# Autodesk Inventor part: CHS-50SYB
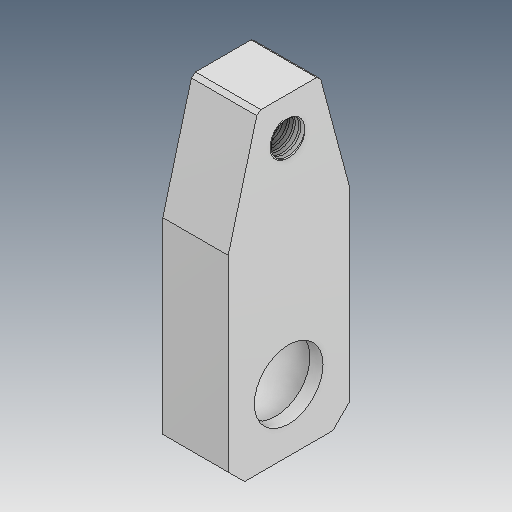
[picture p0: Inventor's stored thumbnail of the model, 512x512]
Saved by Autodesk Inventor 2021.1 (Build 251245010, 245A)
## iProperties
Created: 2021-05
Part Number: CHS-50SYB
Material: Ogólny
Document SubType Name: Modeling
Designer: user
Density: 1 g/cm^3
Appearance: Domyślna
Author: user
Revision Number: ÈÎºÎ
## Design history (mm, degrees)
feature "ÊäÈë1"
node "Bryła1"
